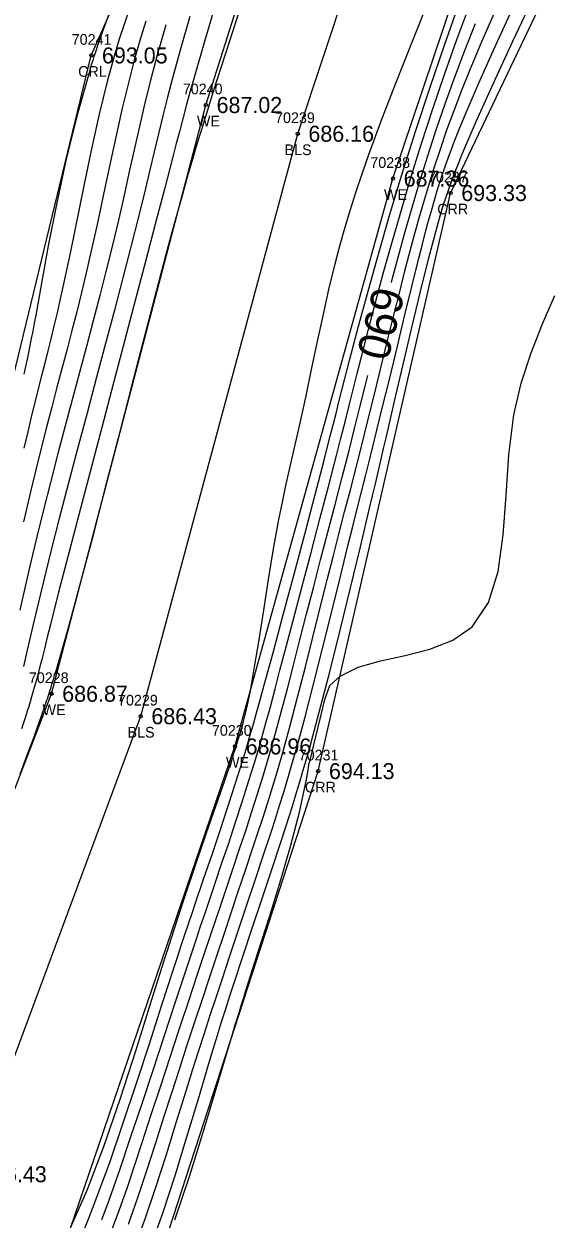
# Model space of a CAD drawing. Extents: x 1376587 to 1378239, y 1000335 to 1003031.
# Drawn here: x 1377568.1 to 1377617.7, y 1001837.8 to 1001949.7 of the extents above; entities that cross this region are included whole.
import ezdxf

# ---------------------------------------------------------------- set-up
doc = ezdxf.new("R2010")
doc.units = 0
for name, color, linetype in [('RD_DTM_BkLn1', 7, 'Continuous'), ('RD_DTM_BkLn_txCode', 7, 'Continuous'), ('RD_DTM_Major1', 7, 'Continuous'), ('RD_DTM_Major1_Lbl', 7, 'Continuous'), ('RD_DTM_Minor1', 7, 'Continuous'), ('RD_EX_H2O', 7, 'Continuous'), ('RD_EX_H2O_txCode', 7, 'Continuous'), ('RD_EX_TX_H2O_ELEV', 7, 'Continuous'), ('RD_EX_TX_Misc_ELEV', 7, 'Continuous'), ('RD_SMD_Locator', 7, 'Continuous')]:
    doc.layers.add(name, color=color, linetype=linetype)

msp = doc.modelspace()

# ---------------------------------------------------------------- linework, layer by layer
at = {"layer": 'RD_DTM_BkLn1'}
msp.add_lwpolyline([(1377383.45, 1001707.4), (1377429.44, 1001729.61), (1377487.4, 1001777.17), (1377524.89, 1001804.33), (1377563.13, 1001842.03), (1377579.05, 1001884.91), (1377593.74, 1001939.44), (1377612.57, 1001996.25), (1377647.79, 1002034.78), (1377670.25, 1002060.61)], dxfattribs=at)
at = {"layer": 'RD_DTM_Major1'}
for points in [[(1377581.4, 1001949.62), (1377581.3, 1001949.3), (1377580.62, 1001946.91), (1377579.99, 1001944.54), (1377579.44, 1001942.33), (1377578.93, 1001940.13), (1377578.43, 1001937.93), (1377577.95, 1001935.74), (1377577.46, 1001933.54), (1377576.96, 1001931.34), (1377576.4, 1001929.01), (1377575.82, 1001926.67), (1377575.22, 1001924.31), (1377574.6, 1001921.93), (1377573.97, 1001919.53), (1377573.32, 1001917.1), (1377572.63, 1001914.54), (1377571.95, 1001911.97), (1377571.27, 1001909.38), (1377570.6, 1001906.8), (1377569.95, 1001904.24), (1377569.33, 1001901.7), (1377568.78, 1001899.35), (1377568.25, 1001897.05), (1377567.75, 1001894.83)], [(1377602.5, 1001925.52), (1377602.61, 1001925.92), (1377603.19, 1001928.1), (1377603.79, 1001930.3), (1377604.43, 1001932.53), (1377605.1, 1001934.79), (1377605.88, 1001937.29), (1377606.7, 1001939.81), (1377607.56, 1001942.33), (1377608.46, 1001944.84), (1377609.39, 1001947.33), (1377610.36, 1001949.76)], [(1377576.39, 1001836.88), (1377577.08, 1001838.74), (1377577.77, 1001840.73), (1377578.47, 1001842.82), (1377579.19, 1001845), (1377580.04, 1001847.63), (1377580.92, 1001850.3), (1377581.81, 1001852.99), (1377582.69, 1001855.66), (1377583.55, 1001858.26), (1377584.37, 1001860.75), (1377584.97, 1001862.55), (1377585.55, 1001864.28), (1377586.11, 1001865.95), (1377586.66, 1001867.59), (1377587.2, 1001869.2), (1377587.73, 1001870.79), (1377588.3, 1001872.49), (1377588.87, 1001874.19), (1377589.43, 1001875.91), (1377589.99, 1001877.65), (1377590.54, 1001879.43), (1377591.08, 1001881.24), (1377591.66, 1001883.31), (1377592.23, 1001885.42), (1377592.8, 1001887.59), (1377593.37, 1001889.8), (1377593.94, 1001892.06), (1377594.53, 1001894.36), (1377595.2, 1001896.94), (1377595.88, 1001899.54), (1377596.56, 1001902.15), (1377597.24, 1001904.74), (1377597.9, 1001907.29), (1377598.54, 1001909.79), (1377599.06, 1001911.83), (1377599.56, 1001913.83), (1377600.05, 1001915.8), (1377600.3, 1001916.8)]]:
    msp.add_lwpolyline(points, dxfattribs=at)
at = {"layer": 'RD_DTM_Minor1'}
for points in [[(1377586.09, 1001951.66), (1377585.01, 1001948.07), (1377584.04, 1001944.72), (1377583.68, 1001943.43), (1377583.34, 1001942.18), (1377583.02, 1001940.96), (1377582.7, 1001939.75), (1377582.38, 1001938.54), (1377582.06, 1001937.29), (1377581.27, 1001934.25), (1377580.41, 1001930.97), (1377579.5, 1001927.49), (1377578.54, 1001923.84), (1377577.54, 1001920.03), (1377576.51, 1001916.12), (1377575.41, 1001911.95), (1377574.32, 1001907.8), (1377573.26, 1001903.77), (1377572.26, 1001899.97), (1377571.37, 1001896.52), (1377570.6, 1001893.51), (1377570.31, 1001892.32), (1377570.04, 1001891.23), (1377569.79, 1001890.23), (1377569.55, 1001889.3), (1377569.32, 1001888.42), (1377569.1, 1001887.59), (1377568.97, 1001887.15), (1377568.84, 1001886.71), (1377568.72, 1001886.27), (1377568.58, 1001885.83), (1377568.44, 1001885.39), (1377568.3, 1001884.95), (1377567.89, 1001883.72)], [(1377576.69, 1001952.38), (1377575.07, 1001947.88), (1377574.94, 1001947.48), (1377574.81, 1001947.08), (1377574.68, 1001946.68), (1377574.56, 1001946.29), (1377574.43, 1001945.89), (1377574.31, 1001945.49), (1377573.1, 1001941.19), (1377572.06, 1001936.93), (1377571.17, 1001932.8), (1377570.41, 1001928.94), (1377569.78, 1001925.45), (1377569.23, 1001922.45), (1377569.09, 1001921.69), (1377568.95, 1001920.97), (1377568.82, 1001920.28), (1377568.69, 1001919.62), (1377568.56, 1001918.96), (1377568.42, 1001918.32), (1377568.28, 1001917.64), (1377568.13, 1001916.94)], [(1377572.46, 1001836.96), (1377574.03, 1001840.53), (1377575.59, 1001844.62), (1377577.12, 1001849.06), (1377578.62, 1001853.67), (1377580.07, 1001858.28), (1377581.47, 1001862.73), (1377581.58, 1001863.07), (1377581.69, 1001863.41), (1377581.8, 1001863.75), (1377581.91, 1001864.09), (1377582.02, 1001864.42), (1377582.12, 1001864.76), (1377583.19, 1001868), (1377584.22, 1001871.06), (1377585.19, 1001873.89), (1377586.08, 1001876.48), (1377586.88, 1001878.81), (1377587.57, 1001880.83), (1377587.63, 1001881.01), (1377587.69, 1001881.19), (1377587.74, 1001881.36), (1377587.8, 1001881.53), (1377587.85, 1001881.69), (1377587.91, 1001881.86), (1377588.18, 1001882.73), (1377588.44, 1001883.58), (1377588.67, 1001884.42), (1377588.89, 1001885.3), (1377589.1, 1001886.25), (1377589.31, 1001887.29), (1377589.71, 1001889.52), (1377590.13, 1001892.07), (1377590.56, 1001894.84), (1377591.01, 1001897.71), (1377591.48, 1001900.58), (1377591.97, 1001903.32), (1377592.3, 1001904.95), (1377592.63, 1001906.51), (1377592.97, 1001908.02), (1377593.31, 1001909.5), (1377593.65, 1001910.99), (1377594, 1001912.5), (1377594.52, 1001914.89), (1377595.04, 1001917.36), (1377595.57, 1001919.87), (1377596.11, 1001922.38), (1377596.66, 1001924.85), (1377597.24, 1001927.26), (1377597.68, 1001928.94), (1377598.14, 1001930.6), (1377598.64, 1001932.26), (1377599.17, 1001933.94), (1377599.76, 1001935.68), (1377600.4, 1001937.51), (1377601.62, 1001940.81), (1377602.97, 1001944.32), (1377604.4, 1001947.94), (1377605.84, 1001951.54)], [(1377573.78, 1001836.92), (1377574.2, 1001837.91), (1377574.62, 1001838.97), (1377575.05, 1001840.12), (1377576.18, 1001843.23), (1377577.38, 1001846.74), (1377578.62, 1001850.46), (1377579.86, 1001854.24), (1377581.04, 1001857.89), (1377582.13, 1001861.24), (1377582.5, 1001862.36), (1377582.85, 1001863.43), (1377583.19, 1001864.46), (1377583.52, 1001865.47), (1377583.85, 1001866.46), (1377584.19, 1001867.45), (1377584.93, 1001869.65), (1377585.69, 1001871.87), (1377586.44, 1001874.11), (1377587.18, 1001876.34), (1377587.9, 1001878.54), (1377588.57, 1001880.7), (1377588.91, 1001881.82), (1377589.24, 1001882.94), (1377589.56, 1001884.07), (1377589.89, 1001885.23), (1377590.22, 1001886.44), (1377590.57, 1001887.71), (1377591.46, 1001890.96), (1377592.41, 1001894.51), (1377593.4, 1001898.22), (1377594.39, 1001901.94), (1377595.33, 1001905.54), (1377596.2, 1001908.88), (1377596.49, 1001910.02), (1377596.77, 1001911.12), (1377597.05, 1001912.19), (1377597.32, 1001913.26), (1377597.59, 1001914.33), (1377597.87, 1001915.42), (1377598.62, 1001918.32), (1377599.43, 1001921.42), (1377600.32, 1001924.71), (1377601.28, 1001928.17), (1377602.32, 1001931.77), (1377603.45, 1001935.49), (1377604.76, 1001939.64), (1377606.13, 1001943.8), (1377607.51, 1001947.84), (1377608.84, 1001951.64)], [(1377579.93, 1001835.11), (1377581.11, 1001838.38), (1377582.27, 1001841.91), (1377583.38, 1001845.54), (1377584.45, 1001849.09), (1377585.43, 1001852.4), (1377585.84, 1001853.75), (1377586.23, 1001855.04), (1377586.62, 1001856.29), (1377587.01, 1001857.51), (1377587.4, 1001858.73), (1377587.8, 1001859.96), (1377588.64, 1001862.51), (1377589.52, 1001865.16), (1377590.42, 1001867.85), (1377591.32, 1001870.56), (1377592.19, 1001873.22), (1377593.02, 1001875.81), (1377593.33, 1001876.8), (1377593.64, 1001877.78), (1377593.93, 1001878.76), (1377594.23, 1001879.76), (1377594.53, 1001880.79), (1377594.83, 1001881.86), (1377595.76, 1001885.3), (1377596.73, 1001889.05), (1377597.71, 1001892.98), (1377598.68, 1001896.93), (1377599.6, 1001900.78), (1377600.46, 1001904.39), (1377600.73, 1001905.54), (1377601, 1001906.66), (1377601.26, 1001907.76), (1377601.52, 1001908.86), (1377601.77, 1001909.97), (1377602.04, 1001911.09), (1377602.8, 1001914.4), (1377603.6, 1001917.84), (1377604.41, 1001921.31), (1377605.22, 1001924.68), (1377606, 1001927.81), (1377606.74, 1001930.59), (1377606.9, 1001931.18), (1377607.07, 1001931.74), (1377607.23, 1001932.29), (1377607.39, 1001932.83), (1377607.56, 1001933.36), (1377607.74, 1001933.88), (1377607.93, 1001934.45), (1377608.14, 1001935.02), (1377608.35, 1001935.6), (1377608.58, 1001936.2), (1377608.83, 1001936.82), (1377609.1, 1001937.47), (1377610.42, 1001940.57), (1377612.04, 1001944.16), (1377613.87, 1001948.12), (1377615.85, 1001952.35)], [(1377588.25, 1001950.93), (1377586.97, 1001946.96), (1377585.84, 1001943.39), (1377585.29, 1001941.65), (1377584.79, 1001940.02), (1377584.31, 1001938.45), (1377583.86, 1001936.92), (1377583.41, 1001935.36), (1377582.95, 1001933.74), (1377582.25, 1001931.21), (1377581.51, 1001928.47), (1377580.72, 1001925.52), (1377579.9, 1001922.38), (1377579.03, 1001919.06), (1377578.13, 1001915.57), (1377576.93, 1001910.93), (1377575.71, 1001906.2), (1377574.5, 1001901.53), (1377573.32, 1001897.1), (1377572.22, 1001893.05), (1377571.23, 1001889.56), (1377571.1, 1001889.13), (1377570.97, 1001888.71), (1377570.85, 1001888.3), (1377570.72, 1001887.9), (1377570.6, 1001887.51), (1377570.48, 1001887.13), (1377570.42, 1001886.92), (1377570.35, 1001886.72), (1377570.29, 1001886.52), (1377570.22, 1001886.32), (1377570.09, 1001885.92), (1377569.52, 1001884.29), (1377568.95, 1001882.69), (1377568.35, 1001881.09), (1377567.74, 1001879.44)], [(1377583.66, 1001950.43), (1377582.8, 1001947.47), (1377582.02, 1001944.63), (1377581.55, 1001942.85), (1377581.13, 1001941.13), (1377580.72, 1001939.44), (1377579.92, 1001936.07), (1377579.51, 1001934.32), (1377578.85, 1001931.66), (1377578.14, 1001928.86), (1377577.39, 1001925.94), (1377576.59, 1001922.92), (1377575.77, 1001919.81), (1377574.92, 1001916.64), (1377574.03, 1001913.29), (1377573.13, 1001909.93), (1377572.26, 1001906.62), (1377571.43, 1001903.42), (1377570.65, 1001900.37), (1377569.95, 1001897.53), (1377569.51, 1001895.72), (1377569.12, 1001894.03), (1377568.75, 1001892.44), (1377568.41, 1001890.96), (1377568.08, 1001889.57)], [(1377577.92, 1001950.87), (1377577.47, 1001949.57), (1377577.05, 1001948.29), (1377576.66, 1001947), (1377576.29, 1001945.68), (1377575.92, 1001944.32), (1377575.18, 1001941.28), (1377574.46, 1001938.04), (1377573.76, 1001934.71), (1377572.44, 1001928.26), (1377571.84, 1001925.38), (1377571.53, 1001923.98), (1377571.23, 1001922.67), (1377570.94, 1001921.44), (1377570.66, 1001920.25), (1377570.37, 1001919.1), (1377570.08, 1001917.96), (1377569.78, 1001916.77), (1377569.47, 1001915.55), (1377569.15, 1001914.28), (1377568.82, 1001912.95), (1377568.48, 1001911.53), (1377568.11, 1001910)], [(1377575.43, 1001837.79), (1377575.98, 1001839.27), (1377576.54, 1001840.85), (1377577.13, 1001842.55), (1377578.11, 1001845.46), (1377579.15, 1001848.57), (1377580.21, 1001851.78), (1377582.29, 1001858.08), (1377583.24, 1001860.98), (1377583.73, 1001862.47), (1377584.2, 1001863.88), (1377584.65, 1001865.24), (1377585.1, 1001866.56), (1377585.54, 1001867.87), (1377585.98, 1001869.18), (1377586.62, 1001871.09), (1377587.28, 1001873.03), (1377587.93, 1001875), (1377588.58, 1001876.98), (1377589.21, 1001878.97), (1377589.81, 1001880.95), (1377590.28, 1001882.55), (1377590.73, 1001884.16), (1377591.18, 1001885.8), (1377591.62, 1001887.48), (1377592.08, 1001889.22), (1377592.56, 1001891.05), (1377593.34, 1001893.99), (1377594.15, 1001897.08), (1377594.99, 1001900.24), (1377595.82, 1001903.38), (1377596.62, 1001906.43), (1377597.36, 1001909.31), (1377597.77, 1001910.93), (1377598.17, 1001912.48), (1377598.55, 1001913.99), (1377599.3, 1001917), (1377599.69, 1001918.54), (1377600.33, 1001921.02), (1377601.01, 1001923.63), (1377601.74, 1001926.36), (1377602.53, 1001929.19), (1377603.37, 1001932.11), (1377604.26, 1001935.11), (1377605.3, 1001938.44), (1377606.39, 1001941.78), (1377607.51, 1001945.07), (1377608.63, 1001948.25), (1377609.75, 1001951.25)], [(1377577.92, 1001837.36), (1377578.76, 1001839.75), (1377579.59, 1001842.28), (1377580.43, 1001844.87), (1377581.25, 1001847.47), (1377581.98, 1001849.73), (1377582.7, 1001851.96), (1377583.41, 1001854.14), (1377584.12, 1001856.3), (1377584.82, 1001858.42), (1377585.51, 1001860.51), (1377586.2, 1001862.58), (1377586.88, 1001864.61), (1377587.55, 1001866.61), (1377588.21, 1001868.58), (1377588.86, 1001870.51), (1377589.49, 1001872.4), (1377589.98, 1001873.89), (1377590.46, 1001875.36), (1377590.93, 1001876.84), (1377591.4, 1001878.35), (1377591.87, 1001879.9), (1377592.34, 1001881.52), (1377593.03, 1001884.03), (1377593.73, 1001886.68), (1377594.43, 1001889.41), (1377595.13, 1001892.19), (1377595.82, 1001894.96), (1377596.5, 1001897.68), (1377597.05, 1001899.84), (1377597.6, 1001901.95), (1377598.13, 1001904.04), (1377598.67, 1001906.11), (1377599.2, 1001908.18), (1377599.73, 1001910.27), (1377600.34, 1001912.72), (1377600.95, 1001915.18), (1377601.56, 1001917.65), (1377602.15, 1001920.08), (1377602.74, 1001922.46), (1377603.31, 1001924.76), (1377603.74, 1001926.47), (1377604.17, 1001928.13), (1377604.6, 1001929.75), (1377605.04, 1001931.35), (1377605.49, 1001932.93), (1377605.96, 1001934.51), (1377606.5, 1001936.24), (1377607.08, 1001938), (1377607.7, 1001939.79), (1377608.36, 1001941.62), (1377609.09, 1001943.51), (1377609.87, 1001945.46), (1377610.97, 1001948.06), (1377612.16, 1001950.75)], [(1377578.47, 1001835.14), (1377579.47, 1001837.85), (1377580.47, 1001840.81), (1377581.45, 1001843.88), (1377582.41, 1001846.96), (1377583.33, 1001849.93), (1377583.9, 1001851.77), (1377584.46, 1001853.53), (1377585.01, 1001855.24), (1377585.55, 1001856.91), (1377586.1, 1001858.58), (1377586.66, 1001860.26), (1377587.42, 1001862.56), (1377588.21, 1001864.9), (1377588.99, 1001867.24), (1377589.77, 1001869.57), (1377590.52, 1001871.84), (1377591.24, 1001874.04), (1377591.65, 1001875.3), (1377592.04, 1001876.55), (1377592.43, 1001877.79), (1377592.82, 1001879.07), (1377593.2, 1001880.38), (1377593.6, 1001881.76), (1377594.4, 1001884.72), (1377595.23, 1001887.92), (1377596.07, 1001891.24), (1377596.9, 1001894.59), (1377597.71, 1001897.87), (1377598.47, 1001900.99), (1377598.9, 1001902.68), (1377599.31, 1001904.32), (1377599.71, 1001905.92), (1377600.11, 1001907.51), (1377600.51, 1001909.12), (1377600.92, 1001910.78), (1377601.62, 1001913.62), (1377602.34, 1001916.57), (1377603.06, 1001919.56), (1377603.77, 1001922.48), (1377604.45, 1001925.25), (1377605.07, 1001927.79), (1377605.38, 1001928.99), (1377605.67, 1001930.12), (1377605.95, 1001931.2), (1377606.24, 1001932.23), (1377606.53, 1001933.23), (1377606.82, 1001934.21), (1377607.17, 1001935.28), (1377607.53, 1001936.37), (1377607.94, 1001937.5), (1377608.38, 1001938.68), (1377608.88, 1001939.93), (1377609.43, 1001941.27), (1377610.65, 1001944.11), (1377612.06, 1001947.26), (1377613.6, 1001950.65)], [(1377579.52, 1001949.98), (1377578.97, 1001948.17), (1377578.45, 1001946.34), (1377577.96, 1001944.44), (1377577.33, 1001941.83), (1377576.72, 1001939.13), (1377576.13, 1001936.39), (1377575.55, 1001933.64), (1377574.97, 1001930.94), (1377574.4, 1001928.34), (1377573.96, 1001926.43), (1377573.51, 1001924.58), (1377573.07, 1001922.78), (1377572.62, 1001921.02), (1377572.16, 1001919.28), (1377571.7, 1001917.54), (1377571.22, 1001915.71), (1377570.73, 1001913.85), (1377570.24, 1001911.96), (1377569.74, 1001910.01), (1377569.24, 1001907.99), (1377568.73, 1001905.9), (1377568.08, 1001903.11)], [(1377582.25, 1001837.76), (1377583.65, 1001841.92), (1377585.02, 1001846.36), (1377586.37, 1001850.87), (1377587.66, 1001855.23), (1377587.87, 1001855.91), (1377588.07, 1001856.58), (1377588.28, 1001857.25), (1377588.48, 1001857.91), (1377588.69, 1001858.57), (1377588.89, 1001859.23), (1377590.01, 1001862.75), (1377591.12, 1001866.22), (1377592.16, 1001869.6), (1377593.11, 1001872.85), (1377593.92, 1001875.94), (1377594.53, 1001878.83), (1377594.59, 1001879.17), (1377594.65, 1001879.51), (1377594.71, 1001879.85), (1377594.76, 1001880.18), (1377594.82, 1001880.51), (1377594.89, 1001880.8), (1377595.24, 1001882.23), (1377595.58, 1001883.64), (1377595.93, 1001885.05), (1377596.28, 1001886.47), (1377596.74, 1001887.78), (1377597.7, 1001888.66), (1377599.4, 1001889.49), (1377601.49, 1001890.08), (1377603.8, 1001890.6), (1377606.11, 1001891.2), (1377608.26, 1001892.04), (1377610.05, 1001893.28), (1377611.59, 1001895.54), (1377612.49, 1001898.47), (1377612.97, 1001901.88), (1377613.23, 1001905.58), (1377613.5, 1001909.39), (1377613.96, 1001913.11), (1377614.65, 1001916.1), (1377615.56, 1001918.93), (1377616.64, 1001921.65), (1377617.8, 1001924.31)]]:
    msp.add_lwpolyline(points, dxfattribs=at)
at = {"layer": 'RD_EX_H2O'}
for points in [[(1377371.25, 1001717.11), (1377416.25, 1001757.3), (1377475.23, 1001784.8), (1377512.74, 1001817.7), (1377552.09, 1001850.9), (1377560.52, 1001889.44), (1377574.43, 1001946.77), (1377597.9, 1001999.75), (1377634.43, 1002044.58), (1377653.84, 1002074.86)], [(1377375.48, 1001712.38), (1377425.1, 1001742.05), (1377446.33, 1001750.64), (1377478.82, 1001780.63), (1377516.49, 1001810.1), (1377555.39, 1001847.34), (1377570.71, 1001887.01), (1377585.15, 1001942.13), (1377603.16, 1001999.03), (1377641.82, 1002043.69), (1377653.81, 1002063.49)], [(1377385.63, 1001693.94), (1377390.69, 1001700.81), (1377433.35, 1001720.08), (1377495.93, 1001770.72), (1377533.61, 1001798.76), (1377554.83, 1001824.25), (1377571.99, 1001835.51), (1377587.87, 1001882.08), (1377602.65, 1001935.24), (1377621.67, 1001991.75), (1377650.41, 1002023.69), (1377680.27, 1002054.33)], [(1377396.05, 1001693.17), (1377435.07, 1001711.76), (1377487.03, 1001748.15), (1377491.03, 1001755.26), (1377495.43, 1001757.76), (1377499.11, 1001765.03), (1377539.31, 1001793.09), (1377579.22, 1001829.19), (1377595.66, 1001879.77), (1377608.04, 1001933.89), (1377632.6, 1001985.4), (1377654.69, 1002020.4), (1377685.95, 1002052.67)]]:
    msp.add_lwpolyline(points, dxfattribs=at)
at = {"layer": 'RD_SMD_Locator'}
for centre in [(1377574.43, 1001946.77), (1377585.15, 1001942.13), (1377593.74, 1001939.44), (1377602.65, 1001935.24), (1377608.04, 1001933.89), (1377570.71, 1001887.01), (1377579.05, 1001884.91), (1377587.87, 1001882.08), (1377595.66, 1001879.77)]:
    msp.add_circle(centre, 0.15, dxfattribs=at)

# ---------------------------------------------------------------- texts
at = {"layer": 'RD_DTM_BkLn_txCode'}
for s, p in [('70239', (1377591.62, 1001940.44)), ('BLS', (1377592.51, 1001937.44)), ('70229', (1377576.93, 1001885.91)), ('BLS', (1377577.82, 1001882.91))]:
    msp.add_text(s, height=1, dxfattribs=at).set_placement(p)
at = {"layer": 'RD_DTM_Major1_Lbl'}
msp.add_text('690', height=3, rotation=255.8203, dxfattribs=at).set_placement((1377600.88, 1001925.29))
at = {"layer": 'RD_EX_H2O_txCode'}
for s, p in [('70241', (1377572.6, 1001947.77)), ('CRL', (1377573.2, 1001944.77)), ('70240', (1377582.99, 1001943.13)), ('WE', (1377584.31, 1001940.13)), ('70238', (1377600.53, 1001936.24)), ('70237', (1377605.92, 1001934.89)), ('WE', (1377601.81, 1001933.24)), ('CRR', (1377606.79, 1001931.89)), ('70228', (1377568.59, 1001888.01)), ('WE', (1377569.87, 1001885.01)), ('70230', (1377585.71, 1001883.08)), ('WE', (1377587.03, 1001880.08)), ('70231', (1377593.83, 1001880.77)), ('CRR', (1377594.41, 1001877.77))]:
    msp.add_text(s, height=1, dxfattribs=at).set_placement(p)
at = {"layer": 'RD_EX_TX_H2O_ELEV'}
for s, p in [('693.05', (1377575.43, 1001946.02)), ('687.02', (1377586.15, 1001941.38)), ('687.36', (1377603.65, 1001934.49)), ('693.33', (1377609.04, 1001933.14)), ('686.87', (1377571.71, 1001886.26)), ('686.96', (1377588.87, 1001881.33)), ('694.13', (1377596.66, 1001879.02))]:
    msp.add_text(s, height=1.5, dxfattribs=at).set_placement(p)
at = {"layer": 'RD_EX_TX_Misc_ELEV'}
for s, p in [('686.16', (1377594.74, 1001938.69)), ('686.43', (1377580.05, 1001884.16)), ('686.43', (1377564.13, 1001841.28))]:
    msp.add_text(s, height=1.5, dxfattribs=at).set_placement(p)

doc.saveas('drawing.dxf')
